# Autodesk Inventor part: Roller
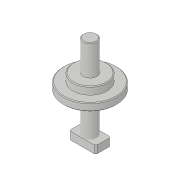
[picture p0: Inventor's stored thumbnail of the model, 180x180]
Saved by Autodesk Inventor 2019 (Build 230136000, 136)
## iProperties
Created: 2018-06
Part Number: Roller
Material: 一般
Document SubType Name: Modeling
Designer: shimont
Density: 1 g/cm^3
Appearance: 既定
Author: ADJ
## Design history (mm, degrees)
sketch "スケッチ1"
  geometry: C1 r 35 at (0, 0); C2 r 9 at (0, 0); C3 r 22.5 at (0, 0); 1 further point
  constraints: 3 centre point, 3 coincident
  dimensions: "d0" = 70 diameter of C1; "d6" = 18 diameter of C2; "d7" = 45 diameter of C3
extrude "押し出し1" new body sketch "スケッチ1" distance "d1" = 10; taper "d2" = 0 deg
extrude "押し出し3" join sketch "スケッチ1" distance "d8" = 20; taper "d9" = 0 deg
extrude "押し出し4" new body sketch "スケッチ1" stored distance "d10" = 120; taper "d11" = 0 deg
chamfer "面取り1" distance "d12" = 1; stored, may be unused: second distance "d13" = 2, angle "d14" = 45 deg
sketch "スケッチ2"
  geometry: L1 (-17.5, 10)-(17.5, 10); L2 (17.5, 10)-(17.5, -10); L3 (17.5, -10)-(-17.5, -10); L4 (-17.5, -10)-(-17.5, 10); L5 (-17.5, 10)-(17.5, -10); L6 (17.5, 10)-(-17.5, -10); 1 further point
  constraints: 12 end point, 2 midpoint, 2 parallel, 1 horizontal, 1 perpendicular
  dimensions: "d15" = 35 distance of L2.end L3.end; "d16" = 20 distance of L1.end L2.end
extrude "押し出し2" new body sketch "スケッチ2" stored distance "d4" = 10; taper "d5" = 0 deg
chamfer "面取り2" distance "d17" = 2; stored, may be unused: second distance "d18" = 2, angle "d19" = 45 deg
node "ソリッド1"
node "ソリッド2"
node "ソリッド3"
